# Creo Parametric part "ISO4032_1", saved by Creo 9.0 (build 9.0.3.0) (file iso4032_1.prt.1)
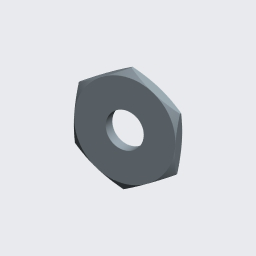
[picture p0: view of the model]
Units: Custom; MM, POUND, SECS

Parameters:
  GEWINDESERIE = "ISO"
  SCHRAUBEN_GROESSE = "M1x.25"
  KLASSE = "H"
  METRISCH = "JA"

Other parameters: STEIGUNG, BOHR_DURCHM, GEWINDEDURCHMESSER, GEWINDEGÄNGE_PRO_INCH, D1, D25, D20

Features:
  1. datum plane "DTM1"
  2. datum plane "DTM2"
  3. datum plane "DTM3"
  4. cut
  5. hole
  6. datum plane "DTM4"
  7. cut
  8. cut

Layers: 32, SAMMELFLÄCHEN

Notes: M1x.25 | GEWINDEBOHREN | DURCH | 0.75 |  BOHREN (  | 0.750 | DURCH |   -(  |  ) BOHRUNG

Family table entries: ISO4032_1M1, ISO4032_1, value(s_val), value(d_val), &_ISO4032_1M1, &PRO_MP_CSYS, data(checksum_info), ISO4032_1M1_2, ISO4032_1, &1_2, &_ISO4032_1M1_2, &PRO_MP_CSYS, ISO4032_1M1_4, ISO4032_1, &1_4, &_ISO4032_1M1_4, &PRO_MP_CSYS, ISO4032_1M1_6, ISO4032_1, &1_6, &_ISO4032_1M1_6, &PRO_MP_CSYS, ISO4032_1M2, ISO4032_1, &_ISO4032_1M2, &PRO_MP_CSYS, ISO4032_1M2_5, ISO4032_1, &2_5, &_ISO4032_1M2_5, &PRO_MP_CSYS, ISO4032_1M3, ISO4032_1, &_ISO4032_1M3, &PRO_MP_CSYS, ISO4032_1M3_5, ISO4032_1, &3_5, &_ISO4032_1M3_5, &PRO_MP_CSYS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

Surfaces: 8 plane, 4 cylinder, 4 cone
